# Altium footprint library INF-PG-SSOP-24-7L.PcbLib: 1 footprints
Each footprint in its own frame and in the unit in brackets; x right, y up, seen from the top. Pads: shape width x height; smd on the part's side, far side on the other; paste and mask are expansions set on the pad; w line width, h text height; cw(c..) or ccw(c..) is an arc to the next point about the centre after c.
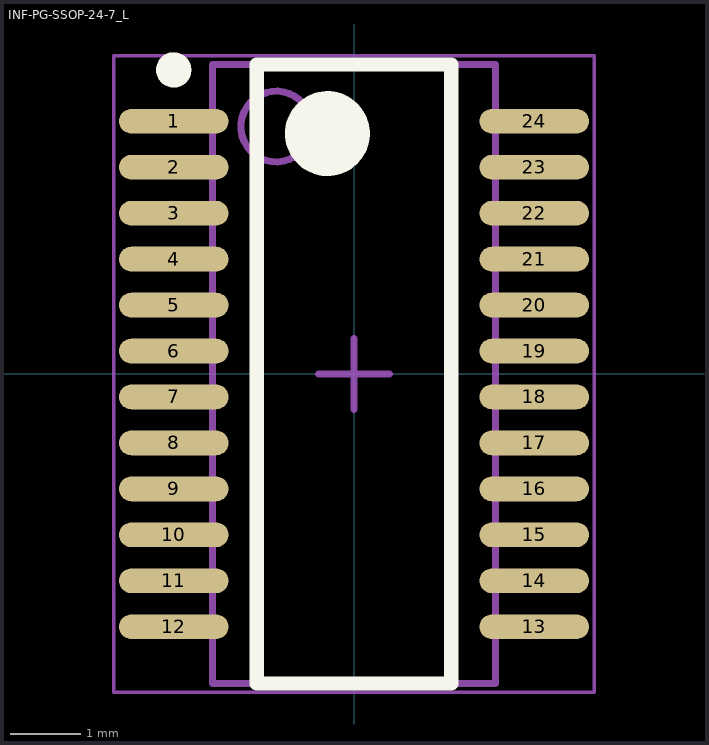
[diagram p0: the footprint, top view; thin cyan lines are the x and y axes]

## INF-PG-SSOP-24-7_L [mm] "SOP, 24-Leads, Body 8.65x3.9mm, Pitch 0.65mm, IPC High Density"
height 1.75
pads (24):
  oval 1.55x0.35 smd: 1(-2.55,3.575) 2(-2.55,2.925) 3(-2.55,2.275) 4(-2.55,1.625) 5(-2.55,0.975) 6(-2.55,0.325) 7(-2.55,-0.325) 8(-2.55,-0.975) 9(-2.55,-1.625) 10(-2.55,-2.275) 11(-2.55,-2.925) 12(-2.55,-3.575) 13(2.55,-3.575) 14(2.55,-2.925) 15(2.55,-2.275) 16(2.55,-1.625) 17(2.55,-0.975) 18(2.55,-0.325) 19(2.55,0.325) 20(2.55,0.975) 21(2.55,1.625) 22(2.55,2.275) 23(2.55,2.925) 24(2.55,3.575)
Top Overlay:
  circle w0.25: c-2.55,4.3 r0.125
  circle w0.6: c-0.375,3.4 r0.3
  lines w0.2: -1.375,-4.375 -1.375,4.375 1.375,4.375 1.375,-4.375 -1.375,-4.375
Mechanical 13:
  circle w0.1: c-1.1,3.5 r0.5
  lines w0.1: -2,-4.375 -2,4.375 2,4.375 2,-4.375 -2,-4.375
Mechanical 15:
  lines w0.05: -3.4,-4.5 -3.4,4.5 3.4,4.5 3.4,-4.5 -3.4,-4.5
  lines w0.1: -0.5,0 0.5,0 ; 0,-0.5 0,0.5
3D body: height 1.75, standoff 0.11, extent -2,-4.375 2,4.375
